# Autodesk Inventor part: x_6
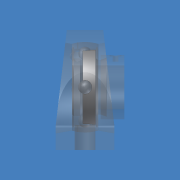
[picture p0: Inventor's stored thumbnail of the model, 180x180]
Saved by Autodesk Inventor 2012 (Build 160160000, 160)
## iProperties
Company: CAD-Verlag
Shininess: 64.0
Length Units: 11269
Angle Units: 11279
Time Units: 11290
Mass Units: 11283
Length Display Precision: 3
Angle Display Precision: 2
Compacted: True
Part Number: x_6
Document SubType Name: Modeling
Created: 2004-09
Material: Standard
Designer: Greiling
Manufacturer: Standard
Standards Organization: Custom
Density: 1 g/cm^3
Density: 0.0
Volumn: 0.0
Area: 0.0
PropertySet Name: Model Information
Control State: 0
Master: False
Checked Out: False
Übersetzungsnorm: STEP AP214CD
Dateiname: w2c22665.stp
Vorprozessor: ACIS
Postprozessor: Build: 081d, Release: 8 SP1 - Date: Tue 01/26/2004
Gesendete Einheiten: MILLIMETERS
Unbestimmtheit: 1e-06
Author: Jürgen Kronas
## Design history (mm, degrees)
feature "Basis1"
node "Volumenkörper1"
node "Volumenkörpern"
node "Oberflächenkörpern"
